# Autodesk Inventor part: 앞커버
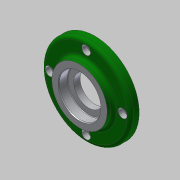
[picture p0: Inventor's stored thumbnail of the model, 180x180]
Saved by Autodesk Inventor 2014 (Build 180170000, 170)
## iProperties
Created: 2019-01
Part Number: 앞커버
Material: 알루미늄 6061
Document SubType Name: Modeling
Designer: mduedu
Density: 1 g/cm^3
Appearance: Aluminum - Flat
Author: mduedu
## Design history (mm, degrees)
sketch "스케치1"
  geometry: L1 (0, 0)-(6, 0); L2 (6, 0)-(6, 25); L3 (6, 25)-(0, 25); L4 (0, 25)-(0, 0); L5 (6, 0)-(14, 0); L6 (14, 0)-(14, 40); L7 (14, 40)-(6, 40); L8 (6, 40)-(6, 0); L9 (14, 0)-(19, 0); L10 (19, 0)-(19, 26); L11 (19, 26)-(14, 26); L12 (14, 26)-(14, 0)
  constraints: 24 end point, 6 parallel, 3 horizontal, 3 perpendicular
  dimensions: "d6" = 80 diameter of L7 L5; "d8" = 50 diameter of L3 L1; "d9" = 52 diameter of L11 L9; "d10" = 5 distance of L10.end L11.end; "d11" = 6 distance of L2.end L3.end; "d12" = 19 distance between parallel lines of L4 L10; "d13" = 8 distance of L6.end L7.end (derived)
revolve "회전1" sketch "스케치1" stored, may be unused: angle "d5" = 90 deg
sketch "스케치2"
  geometry: C1 r 13.5 at (0, 0); 1 further point
  constraints: 1 centre point, 1 coincident
  dimensions: "d14" = 27 diameter of C1
extrude "돌출1" cut sketch "스케치2" stored distance "d15" = 10; taper "d16" = 0 deg
sketch "스케치3" dims "d17" = 66
  geometry: 6 further points
  constraints: 2 vertical alignment, 1 coincident, 7 other
  dimensions: "d20" = 360 deg dimension on point (0, 0) point (0, 33) (derived)
sketch "스케치4"
  geometry: 4 further points
  constraints: 4 other
hole "구멍1" sketch "스케치4" at (-33, 0), (0, -33), (33, 0), (0, 33) diameter "d22" = 4.5; stored, may be unused: countersink angle "d26" = 90 deg, drill point angle "d28" = 0 deg; dims "d23" = 6, "d24" = 8, "d25" = 4.6, "d27" = 8
fillet "모깎기1" dims "d29" = 3
sketch "스케치5"
  geometry: C1 r 19 at (0, 0); 1 further point
  constraints: 1 centre point, 1 coincident
  dimensions: "d30" = 38 diameter of C1
extrude "돌출2" cut sketch "스케치5" distance "d31" = 8.3; taper "d32" = 0 deg
fillet "모깎기2" dims "d33" = 3
chamfer "모따기1" distance "d34" = 0.8; stored, may be unused: second distance "d35" = 2, angle "d36" = 30 deg
fillet "모깎기3" dims "d37" = 0.5
sketch "스케치6"
  geometry: C1 r 22 at (0, 0); 1 further point
  constraints: 1 centre point, 1 coincident
  dimensions: "d38" = 44 diameter of C1
extrude "돌출3" cut sketch "스케치6" distance "d39" = 5; taper "d40" = 0 deg
fillet "모깎기4" dims "d41" = 3
chamfer "모따기2" distance "d42" = 1; stored, may be unused: second distance "d43" = 2, angle "d44" = 30 deg
node "솔리드1"
